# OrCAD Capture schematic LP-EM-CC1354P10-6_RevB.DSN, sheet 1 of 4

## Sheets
1 1_RF: size A3; title: LP-EM-CC1354P10-6
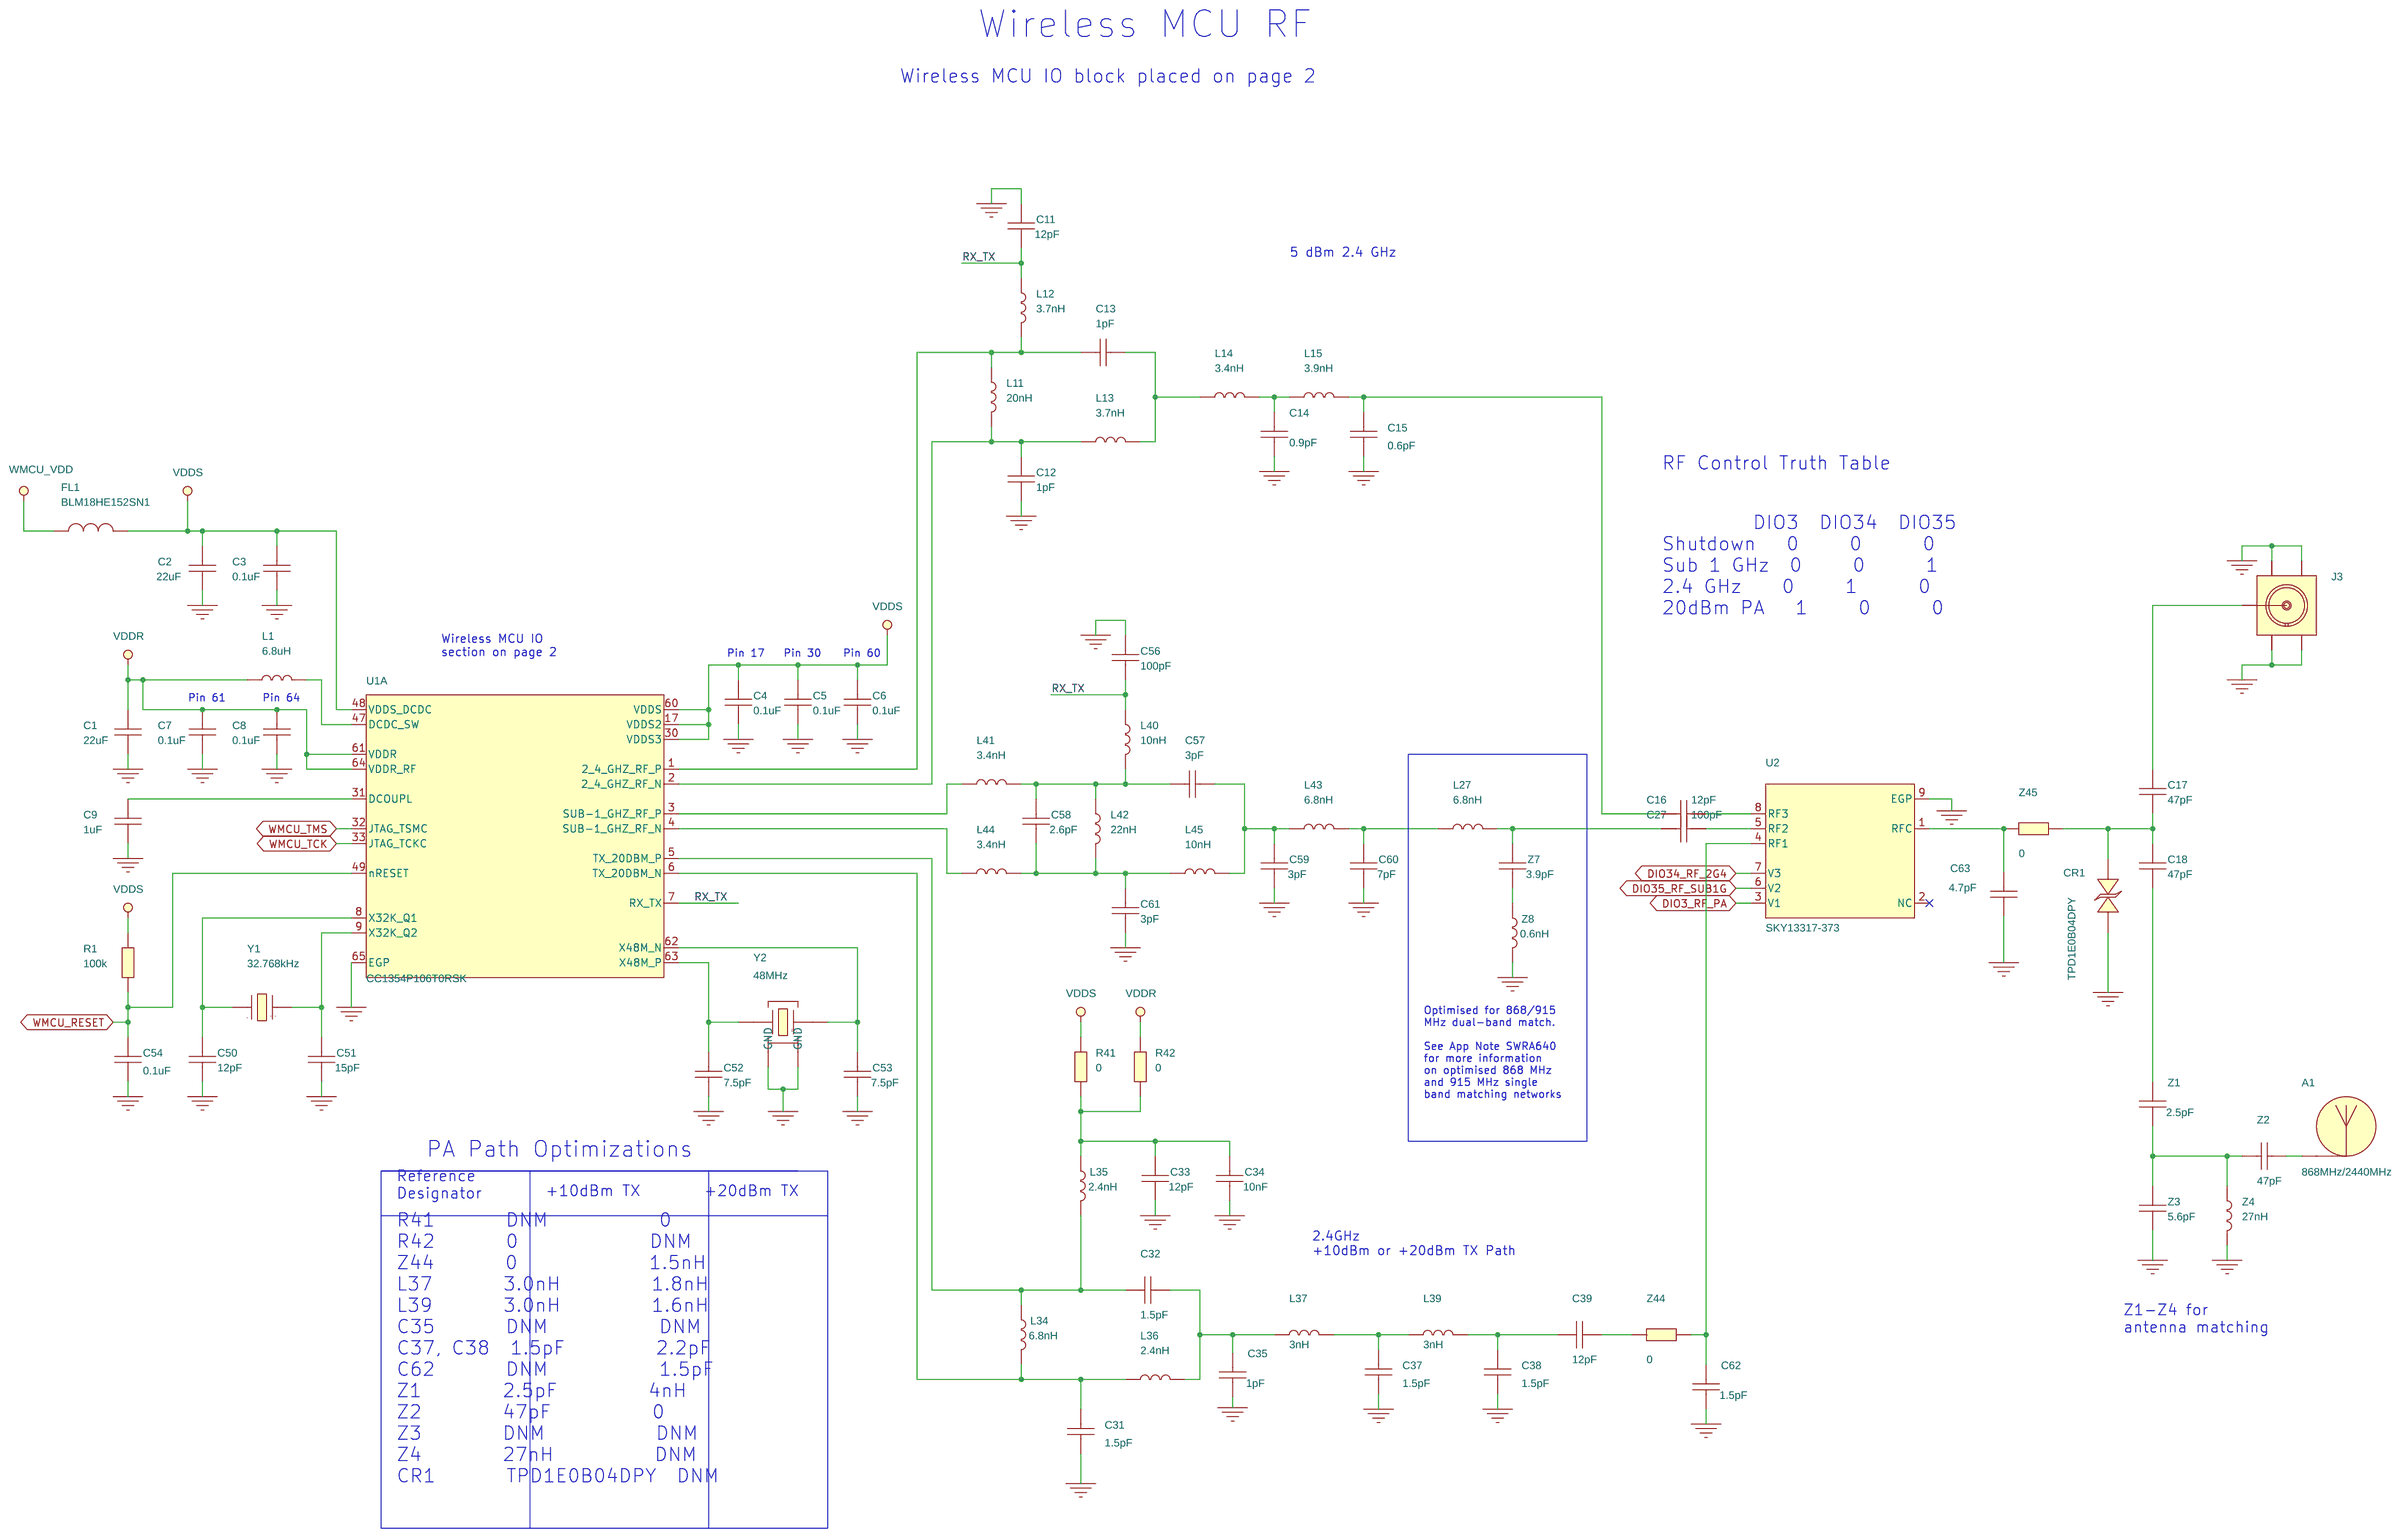
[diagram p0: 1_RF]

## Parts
A1  868MHz/2440MHz  [ANTENNA_DN024N]
C1  22uF  [CAPC1608X100A2N]
C2  22uF  [CAPC1608X100A2N]
C3  0.1uF  [CAPC0603X35B2N]
C4  0.1uF  [CAPC0603X35B2N]
C5  0.1uF  [CAPC0603X35B2N]
C6  0.1uF  [CAPC0603X35B2N]
C7  0.1uF  [CAPC0603X35B2N]
C8  0.1uF  [CAPC0603X35B2N]
C9  1uF  [CAPC0603X40B2N]
C11  12pF  [CAPC0603X35B2N]
C12  1pF  [CAPC0603X35B2N]
C13  1pF  [CAPC0603X35B2N]
C14  0.9pF  [CAPC0603X35B2N]
C15  0.6pF  [CAPC0603X35B2N]
C16  12pF  [CAPC0603X35B2N]
C17  47pF  [CAPC1005X60B2N]
C18  47pF  [CAPC1005X60B2N]
C27  100pF  [CAPC0603X35B2N]
C31  1.5pF  [CAPC0603X35B2N]
C32  1.5pF  [CAPC0603X35B2N]
C33  12pF  [CAPC0603X35B2N]
C34  10nF  [CAPC0603X35B2N]
C35  1pF  [CAPC0603X35B2N]
C37  1.5pF  [CAPC0603X35B2N]
C38  1.5pF  [CAPC0603X35B2N]
C39  12pF  [CAPC0603X35B2N]
C50  12pF  [CAPC0603X35B2N]
C51  15pF  [CAPC0603X35B2N]
C52  7.5pF  [CAPC0603X35B2N]
C53  7.5pF  [CAPC0603X35B2N]
C54  0.1uF  [CAPC0603X35B2N]
C56  100pF  [CAPC0603X35B2N]
C57  3pF  [CAPC0603X35B2N]
C58  2.6pF  [CAPC0603X35B2N]
C59  3pF  [CAPC0603X35B2N]
C60  7pF  [CAPC0603X35B2N]
C61  3pF  [CAPC0603X35B2N]
C62  1.5pF  [CAPC0603X35B2N]
C63  4.7pF  [CAPC0603X35B2N]
CR1  TPD1E0B04DPY  [SON65P100X60X45-2A2N]
FL1  BLM18HE152SN1  [FIL_BLM18HE152SN1DN]
J3  SMA-10V21-TGG  [HUSTSAN_SMA10V21TGGAN]
L1  6.8uH  [INDC2012X150A2N]
L11  20nH  [INDC0603X33A2N]
L12  3.7nH  [INDC0603X33A2N]
L13  3.7nH  [INDC0603X33A2N]
L14  3.4nH  [INDC0603X33A2N]
L15  3.9nH  [IND_LQP03HQ_A2N]
L27  6.8nH  [INDC0603X33A2N]
L34  6.8nH  [INDC0603X33A2N]
L35  2.4nH  [INDC0603X33A2N]
L36  2.4nH  [INDC0603X33A2N]
L37  3nH  [IND_LQP03HQ_A2N]
L39  3nH  [IND_LQP03HQ_A2N]
L40  10nH  [INDC0603X33A2N]
L41  3.4nH  [INDC0603X33A2N]
L42  22nH  [INDC0603X33A2N]
L43  6.8nH  [INDC0603X33A2N]
L44  3.4nH  [INDC0603X33A2N]
L45  10nH  [INDC0603X33A2N]
R1  100k  [RESC1005X40B2N]
R41  0  [RESC1005X40B2N]
R42  0  [RESC1005X40B2N]
U1  CC1354P106T0RSK  [QFNFC40P800X800X100-65A2N]  (sections A,B)
U2  SKY13317-373  [SON40P150X150X50-9A2N]
Y1  32.768kHz  [XTAL_TZ3581F_A2N]
Y2  48MHz  [OSCCC200X160X50-4A2N]
Z1  2.5pF  [CAPC0603X35B2N]
Z2  47pF  [CAPC0603X35B2N]
Z3  5.6pF  [CAPC0603X35B2N]
Z4  27nH  [INDC0603X33A2N]
Z7  3.9pF  [CAPC0603X35B2N]
Z8  0.6nH  [INDC0603X33A2N]
Z44  0  [RESC0603X35B2N]
Z45  0  [RESC0603X35B2N]

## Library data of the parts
A1 = ANTENNA_PCB: ANTENNA, NON COMPONENT, DUAL BAND OPTION - 868MHz/2440MHz, NOT APPLY; Additional Datasheet URL: N/A; AutoDoc File: https://notefied-dynamic-precision.com/DB/Apps/Desktop/Item/Object.aspx?id=96668; BU Name: DYNAMIC PRECISION GDANSK; Budget Currency: N/A; Budget Price: N/A; Client Status: UNDER_REVIEW; Country of Origin: Missing Info; Datasheet URL: https://www.ti.com/lit/an/swra227e/swra227e.pdf; Datasheet URL 1: http://www.ti.com/lit/an/swra227e/swra227e.pdf; Datasheet URL 2: N/A; Mass: N/A; Max Oper Temp: N/A; Maximum Operating Temperature: N/A; Min Oper Temp: N/A; Minimum Operating Temperature: N/A; Mounting Type: NOT APPLY; NOTEfied URL: https://notefied-dynamic-precision.com/NOTEfiedWebInterface/part/show?partNumber=13-01029; Notes: Custom component designed upon client's request.; Packing Size: N/A; Packing Type: Missing Info; Part Number: 13-01029; Part Type: Mechanic|ANTENNA|NON COMPONENT; ROHS: Not Applicable; Revision: R039; RoHS Status: MISSING_INFO; Status: Released; Texas Part Status: Under Review; Type: Mechanic; Vendor: TEXAS INSTRUMENTS; Vendor Part Number: DN024; Vendor Part Status: Active; Weight: N/A
C1 C2 = CAPACITOR: CAPACITOR, CERAMIC X6S, 22uF, 6.3V, -20%/+20%, -55DEGC/+105DEGC, 0603, SMD; ALT_SYMBOLS: CAPC1608X100A2L,CAPC1608X100A2M; Additional Datasheet URL: https://www.murata.com/en-us/products/productdetail?partno=GRM188C80J226ME15%23; AutoDoc File: https://notefied-dynamic-precision.com/DB/Apps/Desktop/Item/Object.aspx?id=104385; BU Name: DYNAMIC PRECISION GDANSK; Budget Currency: EUR; Budget Price: 0.062; Budgetary Price: 0.07648 USD; Client Status: UNDER_REVIEW; Country of Origin: China,Japan,Philippines; Datasheet URL: https://search.murata.co.jp/Ceramy/image/img/A01X/G101/ENG/GRM188C80J226ME15-02A.pdf; Datasheet URL 1: http://psearch.murata.com/capacitor/product/GRM188R60J226MEA0%23.pdf; Datasheet URL 2: http://search.murata.co.jp/Ceramy/image/img/w_hinm/L0005E.pdf; Definied Quality: INDUSTRIAL; Dielectric Type: X6S; Esd Level: N/A; Lead Time: 15; MPN: GRM188R60J106ME47D; MPN Status: NRND; MSL: 1; MTBF: N/A; MTBF Standard: N/A; Manufacturer: MURATA; Mass: 0.0091g; Max Oper Temp: +85DEGC; Max Tol: +20%; Maximum Operating Temperature: +105DEGC; Maximum Tolerance: +20%; Min Oper Temp: -55DEGC; Min Tol: -20%; Minimum Operating Temperature: -55DEGC; Minimum Tolerance: -20%; Mounting Type: SMD; NOTE Status: PREFERRED; NOTEfied URL: https://notefied-dynamic-precision.com/NOTEfiedWebInterface/part/show?partNumber=02-09737; Old Footprint: CAPC1608X90N; PCB Package: 0603; Packing Size: 4000; Packing Type: Tape & Reel; Part Number: 02-09737; Part Type: Capacitor|CERAMIC|0603|STANDARD; REACH/SVHC Compliance: Compliant; REACH/SVHC Details: SVHC List Version Jan 23, 2024 (240); REACH/SVHC Source: REACH Declaration; REACH/SVHC Status: Unaffected; REACH/SVHC_COMPLIANCE: COMPLIANT; REACH/SVHC_DETAILS: SVHC LIST VERSION Dec 17, 2015; REACH/SVHC_SOURCE: REACH DECLARATION; REACH/SVHC_STATUS: UNAFFECTED; ROHS: Compliant; Rated Current: N/A; Rated Voltage: 6.3V; Revision: R019; RoHS Status: ROHS_COMPLIANT; Rtd Voltage: 6.3V; Status: Released; Texas Part Status: Under Review; Type: Capacitor; Vendor: MURATA; Vendor Part Number: GRM188C80J226ME15D; Vendor Part Status: Active; WEIGHT: 0.0091g
C3-C8 C54 = CAPACITOR: CAPACITOR, CERAMIC X7S, 0.1uF, 10V, -10%/+10%, -55DEGC/+125DEGC, 0201, SMD; ALT_SYMBOLS: CAPC0603X35B2L,CAPC0603X35B2M; Additional Datasheet URL: https://www.murata.com/en-us/products/productdetail?partno=GRM033C71A104KE14%23; AutoDoc File: https://notefied-dynamic-precision.com/DB/Apps/Desktop/Item/Object.aspx?id=115293; BU Name: TEXAS INSTRUMENTS NORWAY; Budgetary Price: 0.01328 USD; Client Status: UNDER_REVIEW; Country of Origin: China,Japan,Philippines,Singapore; Datasheet URL: https://search.murata.co.jp/Ceramy/image/img/A01X/G101/ENG/GRM033C71A104KE14-01A.pdf; Datasheet URL 1: http://psearch.en.murata.com/capacitor/product/GRM155R71E104KE14%23.pdf; Datasheet URL 2: http://search.murata.co.jp/Ceramy/image/img/w_hinm/L0005E.pdf; Dielectric Type: X7S; Lead Time: 23; LifeCycle Status: ACTIVE; MPN: GRM155R70J104KA01D; MPN Status: ACTIVE; Manufacturer: MURATA; Mass: 0.00033g; Max Oper Temp: +125DEGC; Max Tol: +10%; Maximum Operating Temperature: +125DEGC; Maximum Tolerance: +10%; Min Oper Temp: -55DEGC; Min Tol: -10%; Minimum Operating Temperature: -55DEGC; Minimum Tolerance: -10%; Mounting Type: SMD; NOTE Status: PREFERRED; NOTEfied URL: https://notefied-dynamic-precision.com/NOTEfiedWebInterface/part/show?partNumber=02-10308; Old Footprint: CAPC1005X60N,0402; PCB Package: 0201; Packing Size: 15000; Packing Type: Tape & Reel; Part Number: 02-10308; Part Type: Capacitor|CERAMIC|0201|STANDARD; REACH/SVHC Compliance: Compliant; REACH/SVHC Details: SVHC List Version Jan 23, 2024 (240); REACH/SVHC Source: REACH Declaration; REACH/SVHC Status: Unaffected; REACH/SVHC_COMPLIANCE: COMPLIANT; REACH/SVHC_DETAILS: SVHC LIST VERSION Jun 20, 2016; REACH/SVHC_SOURCE: REACH DECLARATION; REACH/SVHC_STATUS: UNAFFECTED; ROHS: Compliant; Rated Voltage: 10V; Revision: R018; RoHS Status: ROHS_COMPLIANT; Rtd Voltage: 25V; Status: Released; Texas Part Status: Under Review; Type: Capacitor; Vendor: MURATA; Vendor Part Number: GRM033C71A104KE14D; Vendor Part Status: Active; WEIGHT: 0.0016g
C9 = CAPACITOR: CAPACITOR, CERAMIC X6S, 1uF, 6.3V, -20%/+20%, -55DEGC/+105DEGC, 0201, SMD; ALT_SYMBOLS: CAPC0603X40B2L,CAPC0603X40B2M; Additional Datasheet URL: https://www.murata.com/en-us/products/productdetail?partno=GRM033C80J105ME05%23; AutoDoc File: https://notefied-dynamic-precision.com/DB/Apps/Desktop/Item/Object.aspx?id=115295; BU Name: TEXAS INSTRUMENTS NORWAY; Budgetary Price: 0.0415 USD; Client Status: UNDER_REVIEW; Country of Origin: China,Japan,Philippines; Datasheet URL: https://search.murata.co.jp/Ceramy/image/img/A01X/G101/ENG/GRM033C80J105ME05-01A.pdf; Datasheet URL 1: http://psearch.en.murata.com/capacitor/product/GRM155R61C105KA12%23.pdf; Datasheet URL 2: http://search.murata.co.jp/Ceramy/image/img/w_hinm/L0005E.pdf; Definied Quality: INDUSTRIAL; Dielectric Type: X6S; Esd Level: N/A; Lead Time: 11; MPN: GRM155R61A105KE15D; MPN Status: ACTIVE; MSL: 1; MTBF: N/A; MTBF Standard: N/A; Manufacturer: MURATA; Mass: 0.00033g; Max Oper Temp: +85DEGC; Max Tol: +10%; Maximum Operating Temperature: +105DEGC; Maximum Tolerance: +20%; Min Oper Temp: -55DEGC; Min Tol: -10%; Minimum Operating Temperature: -55DEGC; Minimum Tolerance: -20%; Mounting Type: SMD; NOTE Status: PREFERRED; NOTEfied URL: https://notefied-dynamic-precision.com/NOTEfiedWebInterface/part/show?partNumber=02-09405; Old Footprint: CAPC1005X60N,0402; PCB Package: 0201; Packing Size: 15000; Packing Type: Tape & Reel; Part Number: 02-09405; Part Type: Capacitor|CERAMIC|0201|STANDARD; REACH/SVHC Compliance: Compliant; REACH/SVHC Details: SVHC List Version Jan 23, 2024 (240); REACH/SVHC Source: REACH Declaration; REACH/SVHC Status: Unaffected; REACH/SVHC_COMPLIANCE: COMPLIANT; REACH/SVHC_DETAILS: SVHC LIST VERSION Jun 20, 2016; REACH/SVHC_SOURCE: REACH DECLARATION; REACH/SVHC_STATUS: UNAFFECTED; ROHS: Compliant; Rated Voltage: 6.3V; Revision: R024; RoHS Status: ROHS_COMPLIANT; Rtd Voltage: 16V; Status: Released; Texas Part Status: Under Review; Type: Capacitor; Vendor: MURATA; Vendor Part Number: GRM033C80J105ME05D; Vendor Part Status: Active; WEIGHT: 0.0016g
C11 C16 = CAPACITOR: CAPACITOR, CERAMIC C0G/NP0, 12pF, 50V, -2%/+2%, -55DEGC/+125DEGC, 0201, SMD; ALT_SYMBOLS: CAPC0603X35B2L,CAPC0603X35B2M; Additional Datasheet URL: https://search.murata.co.jp/Ceramy/image/img/A01X/G101/ENG/GRM0335C1H120GA01-01A.pdf; Budgetary Price: 0.00506 USD; Datasheet URL: https://www.murata.com/-/media/webrenewal/support/library/catalog/products/capacitor/ceramiccapacitor/c02e.ashx?la=en-gb&cvid=20210120024548000000; Dielectric Type: C0G/NP0; Lead Time: 23; Mass: 0.00033g; Maximum Operating Temperature: +125DEGC; Maximum Tolerance: +2%; Minimum Operating Temperature: -55DEGC; Minimum Tolerance: -2%; Mounting Type: SMD; NOTEfied URL: https://notefied-dynamic-precision.com/NOTEfiedWebInterface/part/show?partNumber=02-10307; PCB Package: 0201; Packing Size: 15000; Packing Type: Tape & Reel; Part Number: 02-10307; Part Type: Capacitor|CERAMIC|0201|STANDARD; REACH/SVHC Compliance: Compliant; REACH/SVHC Details: SVHC List Version Jan 19, 2021; REACH/SVHC Source: REACH Declaration; REACH/SVHC Status: Unaffected; ROHS: Compliant; Rated Voltage: 50V; Revision: R001; Status: Released; Texas Part Status: Under Review; Type: Capacitor; Vendor: MURATA; Vendor Part Number: GRM0335C1H120GA01D; Vendor Part Status: Active
C12 C13 = CAPACITOR: CAPACITOR, CERAMIC C0G/NP0, 1pF, 50V, -0.1pF/+0.1pF, -55DEGC/+125DEGC, 0201, SMD; ALT_SYMBOLS: CAPC0603X35B2L,CAPC0603X35B2M; Additional Datasheet URL: https://search.murata.co.jp/Ceramy/image/img/A01X/G101/ENG/GRM0335C1H1R0BA01-01A.pdf; AutoDoc File: https://notefied-dynamic-precision.com/DB/Apps/Desktop/Item/Object.aspx?id=97010; BU Name: DYNAMIC PRECISION GDANSK; Budget Currency: EUR; Budget Price: 0.00597; Budgetary Price: 0.01 EUR; Client Status: UNDER_REVIEW; Country of Origin: Missing Info; Datasheet URL: https://www.murata.com/-/media/webrenewal/support/library/catalog/products/capacitor/mlcc/c02e.ashx?la=en-gb; Datasheet URL 1: http://psearch.murata.com/capacitor/product/GRM0335C1H1R1BA01%23.pdf; Datasheet URL 2: http://psearch.en.murata.com/capacitor/product/GRM0335C1H1R1BA01%23.html; Dielectric Type: C0G/NP0; Lead Time: 24; MPN: GRM1555C1H1R0CA01D; MPN Status: ACTIVE; Manufacturer: MURATA; Mass: 0.00033g; Max Oper Temp: +125DEGC; Max Tol: +0.1pF; Maximum Operating Temperature: +125DEGC; Maximum Tolerance: +0.1pF; Min Oper Temp: -55DEGC; Min Tol: -0.1pF; Minimum Operating Temperature: -55DEGC; Minimum Tolerance: -0.1pF; Mounting Type: SMD; NOTE Status: PREFERRED; NOTEfied URL: https://notefied-dynamic-precision.com/NOTEfiedWebInterface/part/show?partNumber=02-06124; Old Footprint: CAPC1005X60N; PCB Package: 0201; Packing Size: 50000; Packing Type: Tape & Reel; Part Number: 02-06124; Part Type: Capacitor|CERAMIC|0201|STANDARD; REACH/SVHC Compliance: Compliant; REACH/SVHC Details: SVHC List Version Jul 7, 2017; REACH/SVHC Source: REACH Declaration; REACH/SVHC Status: Unaffected; REACH/SVHC_COMPLIANCE: COMPLIANT; REACH/SVHC_DETAILS: SVHC List Version Jan 12, 2017; REACH/SVHC_SOURCE: REACH DECLARATION; REACH/SVHC_STATUS: UNAFFECTED; ROHS: Compliant; Rated Voltage: 50V; Revision: R025; RoHS Status: ROHS_COMPLIANT; Rtd Voltage: 50V; Status: Released; Texas Part Status: Under Review; Type: Capacitor; Vendor: MURATA; Vendor Part Number: GRM0335C1H1R0BA01J; Vendor Part Status: Active; WEIGHT: 0.00033g
C14 = CAPACITOR: CAPACITOR, CERAMIC C0G/NP0, 0.9pF, 50V, -0.1pF/+0.1pF, -55DEGC/+125DEGC, 0201, SMD; ALT_SYMBOLS: CAPC0603X35B2L,CAPC0603X35B2M; Additional Datasheet URL: https://www.murata.com/en-us/products/productdetail?partno=GRM0335C1HR90BA01%23; Budgetary Price: 0.00272 USD; Country of Origin: China,Japan; Datasheet URL: https://search.murata.co.jp/Ceramy/image/img/A01X/G101/ENG/GRM0335C1HR90BA01-01A.pdf; Dielectric Type: C0G/NP0; Lead Time: 11; Mass: 0.00033g; Maximum Operating Temperature: +125DEGC; Maximum Tolerance: +0.1pF; Minimum Operating Temperature: -55DEGC; Minimum Tolerance: -0.1pF; Mounting Type: SMD; NOTEfied URL: https://notefied-dynamic-precision.com/NOTEfiedWebInterface/part/show?partNumber=02-06123; PCB Package: 0201; Packing Size: 50000; Packing Type: Tape & Reel; Part Number: 02-06123; Part Type: Capacitor|CERAMIC|0201|STANDARD; REACH/SVHC Compliance: Compliant; REACH/SVHC Details: SVHC List Version Jan 23, 2024 (240); REACH/SVHC Source: REACH Declaration; REACH/SVHC Status: Unaffected; ROHS: Compliant; Rated Voltage: 50V; Revision: R041; Status: Released; Texas Part Status: Under Review; Type: Capacitor; Vendor: MURATA; Vendor Part Number: GRM0335C1HR90BA01J; Vendor Part Status: Active
C15 = CAPACITOR: CAPACITOR, CERAMIC C0G/NP0, 0.6pF, 50V, -0.1pF/+0.1pF, -55DEGC/+125DEGC, 0201, SMD; ALT_SYMBOLS: CAPC0603X35B2L,CAPC0603X35B2M; Additional Datasheet URL: https://www.murata.com/en-us/products/productdetail?partno=GRM0335C1HR60BA01%23; Budgetary Price: 0.00272 USD; Country of Origin: China,Japan; Datasheet URL: https://search.murata.co.jp/Ceramy/image/img/A01X/G101/ENG/GRM0335C1HR60BA01-01A.pdf; Dielectric Type: C0G/NP0; Lead Time: 11; Mass: 0.00033g; Maximum Operating Temperature: +125DEGC; Maximum Tolerance: +0.1pF; Minimum Operating Temperature: -55DEGC; Minimum Tolerance: -0.1pF; Mounting Type: SMD; NOTEfied URL: https://notefied-dynamic-precision.com/NOTEfiedWebInterface/part/show?partNumber=02-06120; PCB Package: 0201; Packing Size: 50000; Packing Type: Tape & Reel; Part Number: 02-06120; Part Type: Capacitor|CERAMIC|0201|STANDARD; REACH/SVHC Compliance: Compliant; REACH/SVHC Details: SVHC List Version Jan 23, 2024 (240); REACH/SVHC Source: REACH Declaration; REACH/SVHC Status: Unaffected; ROHS: Compliant; Rated Voltage: 50V; Revision: R041; Status: Released; Texas Part Status: Under Review; Type: Capacitor; Vendor: MURATA; Vendor Part Number: GRM0335C1HR60BA01J; Vendor Part Status: Active
C17 = CAPACITOR: CAPACITOR, CERAMIC C0G/NP0, 47pF, 50V, -5%/+5%, -55DEGC/+125DEGC, 0402, SMD; Additional Datasheet URL: https://search.murata.co.jp/Ceramy/image/img/A01X/G101/ENG/GCM1555C1H470JA16-01.pdf; AutoDoc File: https://notefied-dynamic-precision.com/DB/Apps/Desktop/Item/Object.aspx?id=113344; BU Name: TEXAS INSTRUMENTS NORWAY; Budgetary Price: 0.01416 USD; Datasheet URL: https://www.murata.com/-/media/webrenewal/support/library/catalog/products/capacitor/ceramiccapacitor/c03e.ashx?la=en-gb&cvid=20200707014404000000; Datasheet URL 1: N/A; Datasheet URL 2: N/A; Dielectric Type: C0G/NP0; Lead Time: 27; Mass: 0.0016g; Max Oper Temp: +125DEGC; Maximum Operating Temperature: +125DEGC; Maximum Tolerance: +5%; Min Oper Temp: -55DEGC; Minimum Operating Temperature: -55DEGC; Minimum Tolerance: -5%; Mounting Type: SMD; NOTEfied URL: https://notefied-dynamic-precision.com/NOTEfiedWebInterface/part/show?partNumber=02-10309; PCB Package: 0402; Packing Size: 50000; Packing Type: Tape & Reel; Part Number: 02-10309; Part Type: Capacitor|CERAMIC|0402|STANDARD; REACH/SVHC Compliance: Compliant; REACH/SVHC Details: SVHC List Version Jan 19, 2021; REACH/SVHC Source: REACH Declaration; REACH/SVHC Status: Unaffected; ROHS: Compliant; Rated Voltage: 50V; Revision: R001; RoHS Status: ROHS_COMPLIANT; Status: Released; Texas Part Status: Under Review; Type: Capacitor; Vendor: MURATA; Vendor Part Number: GCM1555C1H470JA16J; Vendor Part Status: Active; Weight: N/A
C18 = CAPACITOR: CAPACITOR, CERAMIC C0G/NP0, 47pF, 50V, -5%/+5%, -55DEGC/+125DEGC, 0402, SMD; Additional Datasheet URL: https://search.murata.co.jp/Ceramy/image/img/A01X/G101/ENG/GCM1555C1H470JA16-01.pdf; Budgetary Price: 0.01416 USD; Datasheet URL: https://www.murata.com/-/media/webrenewal/support/library/catalog/products/capacitor/ceramiccapacitor/c03e.ashx?la=en-gb&cvid=20200707014404000000; Dielectric Type: C0G/NP0; Lead Time: 27; Mass: 0.0016g; Maximum Operating Temperature: +125DEGC; Maximum Tolerance: +5%; Minimum Operating Temperature: -55DEGC; Minimum Tolerance: -5%; Mounting Type: SMD; NOTEfied URL: https://notefied-dynamic-precision.com/NOTEfiedWebInterface/part/show?partNumber=02-10309; PCB Package: 0402; Packing Size: 50000; Packing Type: Tape & Reel; Part Number: 02-10309; Part Type: Capacitor|CERAMIC|0402|STANDARD; REACH/SVHC Compliance: Compliant; REACH/SVHC Details: SVHC List Version Jan 19, 2021; REACH/SVHC Source: REACH Declaration; REACH/SVHC Status: Unaffected; ROHS: Compliant; Rated Voltage: 50V; Revision: R001; Status: Released; Texas Part Status: Under Review; Type: Capacitor; Vendor: MURATA; Vendor Part Number: GCM1555C1H470JA16J; Vendor Part Status: Active
C27 = CAPACITOR: CAPACITOR, CERAMIC C0G/NP0, 100pF, 50V, -2%/+2%, -55DEGC/+125DEGC, 0201, SMD; ALT_SYMBOLS: CAPC0603X35B2L,CAPC0603X35B2M; Additional Datasheet URL: https://search.murata.co.jp/Ceramy/image/img/A01X/G101/ENG/GRM0335C1H101GA01-01A.pdf; AutoDoc File: https://notefied-dynamic-precision.com/DB/Apps/Desktop/Item/Object.aspx?id=116466; BU Name: DYNAMIC PRECISION GDANSK; Budgetary Price: 0.0032 USD; Client Status: UNDER_REVIEW; Country of Origin: China,Philippines; Datasheet URL: https://www.murata.com/-/media/webrenewal/support/library/catalog/products/capacitor/mlcc/c02e.ashx?la=en-gb; Datasheet URL 1: http://www.murata.com/~/media/webrenewal/support/library/catalog/products/capacitor/mlcc/c02e.ashx?la=en-gb; Datasheet URL 2: http://psearch.en.murata.com/capacitor/product/GRM0335C1H101GA01%23.pdf; Dielectric Type: C0G/NP0; Lead Time: 11; Mass: 0.00033g; Max Oper Temp: +125DEGC; Max Tol: +2%; Maximum Operating Temperature: +125DEGC; Maximum Tolerance: +2%; Min Oper Temp: -55DEGC; Min Tol: -2%; Minimum Operating Temperature: -55DEGC; Minimum Tolerance: -2%; Mounting Type: SMD; NOTEfied URL: https://notefied-dynamic-precision.com/NOTEfiedWebInterface/part/show?partNumber=02-07975; PCB Package: 0201; Packing Size: 15000; Packing Type: Tape & Reel; Part Number: 02-07975; Part Type: Capacitor|CERAMIC|0201|STANDARD; ROHS: Compliant; Rated Voltage: 50V; Revision: R021; RoHS Status: ROHS_COMPLIANT; Rtd Voltage: 50V; Status: Released; Type: Capacitor; Vendor: MURATA; Vendor Part Number: GRM0335C1H101GA01D; Vendor Part Status: Active; Weight: 0.00033g
C31 C32 C37 C38 = CAPACITOR: CAPACITOR, CERAMIC C0G/NP0, 1.5pF, 50V, -0.1pF/+0.1pF, -55DEGC/+125DEGC, 0201, SMD; ALT_SYMBOLS: CAPC0603X35B2L,CAPC0603X35B2M; Additional Datasheet URL: https://www.murata.com/en-us/products/productdetail?partno=GRM0335C1H1R5BA01%23; Budgetary Price: 0.00272 USD; Country of Origin: China,Japan,Philippines; Datasheet URL: https://search.murata.co.jp/Ceramy/image/img/A01X/G101/ENG/GRM0335C1H1R5BA01-01A.pdf; Dielectric Type: C0G/NP0; Lead Time: 11; Mass: 0.00033g; Maximum Operating Temperature: +125DEGC; Maximum Tolerance: +0.1pF; Minimum Operating Temperature: -55DEGC; Minimum Tolerance: -0.1pF; Mounting Type: SMD; NOTEfied URL: https://notefied-dynamic-precision.com/NOTEfiedWebInterface/part/show?partNumber=02-06129; PCB Package: 0201; Packing Size: 50000; Packing Type: Tape & Reel; Part Number: 02-06129; Part Type: Capacitor|CERAMIC|0201|STANDARD; REACH/SVHC Compliance: Compliant; REACH/SVHC Details: SVHC List Version Jan 23, 2024 (240); REACH/SVHC Source: REACH Declaration; REACH/SVHC Status: Unaffected; ROHS: Compliant; Rated Voltage: 50V; Revision: R041; Status: Released; Texas Part Status: Under Review; Type: Capacitor; Vendor: MURATA; Vendor Part Number: GRM0335C1H1R5BA01J; Vendor Part Status: Active
C33 C39 = CAPACITOR: CAPACITOR, CERAMIC C0G/NP0, 12pF, 50V, -1%/+1%, -55DEGC/+125DEGC, 0201, SMD; ALT_SYMBOLS: CAPC0603X35B2L,CAPC0603X35B2M; Additional Datasheet URL: https://www.murata.com/en-us/products/productdetail?partno=GRT0335C1H120FA02%23; Budgetary Price: 0.00504 USD; Country of Origin: Missing Info; Datasheet URL: https://search.murata.co.jp/Ceramy/image/img/A01X/G101/ENG/GRT0335C1H120FA02-01A.pdf; Dielectric Type: C0G/NP0; Lead Time: 148; Mass: 0.00033g; Maximum Operating Temperature: +125DEGC; Maximum Tolerance: +1%; Minimum Operating Temperature: -55DEGC; Minimum Tolerance: -1%; Mounting Type: SMD; NOTEfied URL: https://notefied-dynamic-precision.com/NOTEfiedWebInterface/part/show?partNumber=02-10513; PCB Package: 0201; Packing Size: 15000; Packing Type: Tape & Reel; Part Number: 02-10513; Part Type: Capacitor|CERAMIC|0201|PRECISION; REACH/SVHC Compliance: Compliant; REACH/SVHC Details: SVHC List Version Jan 23, 2024 (240); REACH/SVHC Source: REACH Declaration; REACH/SVHC Status: Unaffected; ROHS: Compliant; Rated Voltage: 50V; Revision: R015; Status: Released; Texas Part Status: Under Review; Type: Capacitor; Vendor: MURATA; Vendor Part Number: GRT0335C1H120FA02D; Vendor Part Status: Active
C34 = CAPACITOR: CAPACITOR, CERAMIC X7R, 10nF, 10V, -10%/+10%, -55DEGC/+125DEGC, 0201, SMD; ALT_SYMBOLS: CAPC0603X35B2L,CAPC0603X35B2M; Additional Datasheet URL: https://www.murata.com/en-us/products/productdetail?partno=GRM033R71A103KA01%23; AutoDoc File: https://notefied-dynamic-precision.com/DB/Apps/Desktop/Item/Object.aspx?id=49750; BU Name: DYNAMIC PRECISION GDANSK; Budget Currency: EUR; Budget Price: 0.007; Budgetary Price: 0.0042 USD; Client Status: UNDER_REVIEW; Country of Origin: China,Japan,Philippines; Datasheet URL: https://search.murata.co.jp/Ceramy/image/img/A01X/G101/ENG/GRM033R71A103KA01-01A.pdf; Datasheet URL 1: http://psearch.murata.com/capacitor/product/GRM033R71A103KA01%23.pdf; Datasheet URL 2: http://search.murata.co.jp/Ceramy/image/img/w_hinm/L0005E.pdf; Dielectric Type: X7R; Lead Time: 11; Mass: 0.00033g; Max Oper Temp: +125DEGC; Max Tol: +10%; Maximum Operating Temperature: +125DEGC; Maximum Tolerance: +10%; Min Oper Temp: -55DEGC; Min Tol: -10%; Minimum Operating Temperature: -55DEGC; Minimum Tolerance: -10%; Mounting Type: SMD; NOTEfied URL: https://notefied-dynamic-precision.com/NOTEfiedWebInterface/part/show?partNumber=02-00599; PCB Package: 0201; Packing Size: 15000; Packing Type: Tape & Reel; Part Number: 02-00599; Part Type: Capacitor|CERAMIC|0201|STANDARD; REACH/SVHC Compliance: Compliant; REACH/SVHC Details: SVHC List Version Jan 23, 2024 (240); REACH/SVHC Source: REACH Declaration & Material Declaration; REACH/SVHC Status: Unaffected; REACH/SVHC_COMPLIANCE: COMPLIANT; REACH/SVHC_DETAILS: SVHC List Version Jan 12, 2017; REACH/SVHC_SOURCE: REACH DECLARATION; REACH/SVHC_STATUS: UNAFFECTED; ROHS: Compliant; Rated Voltage: 10V; Revision: R049; RoHS Status: ROHS_COMPLIANT; Rtd Voltage: 10V; Status: Released; Type: Capacitor; Vendor: MURATA; Vendor Part Number: GRM033R71A103KA01D; Vendor Part Status: Active; Weight: 0.00033g
C35 = CAPACITOR: CAPACITOR, CERAMIC C0G/NP0, 1pF, 50V, -0.1pF/+0.1pF, -55DEGC/+125DEGC, 0201, SMD; ALT_SYMBOLS: CAPC0603X35B2L,CAPC0603X35B2M; Additional Datasheet URL: https://www.murata.com/en-eu/products/productdetail?partno=GRM0335C1H1R0BA01%23; Budgetary Price: 0.01 EUR; Country of Origin: China,Japan,Philippines; Datasheet URL: https://search.murata.co.jp/Ceramy/image/img/A01X/G101/ENG/GRM0335C1H1R0BA01-01A.pdf; Dielectric Type: C0G/NP0; Lead Time: 24; Mass: 0.00033g; Maximum Operating Temperature: +125DEGC; Maximum Tolerance: +0.1pF; Minimum Operating Temperature: -55DEGC; Minimum Tolerance: -0.1pF; Mounting Type: SMD; NOTEfied URL: https://notefied-dynamic-precision.com/NOTEfiedWebInterface/part/show?partNumber=02-06124; PCB Package: 0201; Packing Size: 50000; Packing Type: Tape & Reel; Part Number: 02-06124; Part Type: Capacitor|CERAMIC|0201|STANDARD; REACH/SVHC Compliance: Compliant; REACH/SVHC Details: SVHC List Version Jul 7, 2017; REACH/SVHC Source: REACH Declaration; REACH/SVHC Status: Unaffected; ROHS: Compliant; Rated Voltage: 50V; Revision: R037; Status: Released; Texas Part Status: Under Review; Type: Capacitor; Vendor: MURATA; Vendor Part Number: GRM0335C1H1R0BA01J; Vendor Part Status: Active
C50 = CAPACITOR: CAPACITOR, CERAMIC C0G/NP0, 12pF, 50V, -2%/+2%, -55DEGC/+125DEGC, 0201, SMD; ALT_SYMBOLS: CAPC0603X35B2L,CAPC0603X35B2M; Additional Datasheet URL: https://www.murata.com/en-us/products/productdetail?partno=GRM0335C1H120GA01%23; AutoDoc File: https://notefied-dynamic-precision.com/DB/Apps/Desktop/Item/Object.aspx?id=113345; BU Name: TEXAS INSTRUMENTS NORWAY; Budget Currency: EUR; Budget Price: 0.007; Budgetary Price: 0.00506 USD; Country of Origin: China,Japan,Philippines; Datasheet URL: https://search.murata.co.jp/Ceramy/image/img/A01X/G101/ENG/GRM0335C1H120GA01-01A.pdf; Datasheet URL 1: http://psearch.murata.com/capacitor/product/GRM1555C1H120JA01%23.pdf; Datasheet URL 2: http://search.murata.co.jp/Ceramy/image/img/w_hinm/L0005E.pdf; Definied Quality: INDUSTRIAL; Dielectric Type: C0G/NP0; Esd Level: N/A; Lead Time: 23; LifeCycle Status: ACTIVE; MPN: CAPACITOR_0402_12pF_C0G/NP0_M_+/-5%_50V; MPN Status: ACTIVE; MSL: N/A; MTBF: N/A; MTBF Standard: N/A; Manufacturer: MANUFACTURER SELECTION; Mass: 0.00033g; Max Oper Temp: +125DEGC; Max Tol: +5%; Maximum Operating Temperature: +125DEGC; Maximum Tolerance: +2%; Min Oper Temp: -55DEGC; Min Tol: -5%; Minimum Operating Temperature: -55DEGC; Minimum Tolerance: -2%; Mounting Type: SMD; NOTE Status: PREFERRED; NOTEfied URL: https://notefied-dynamic-precision.com/NOTEfiedWebInterface/part/show?partNumber=02-10307; Old Footprint: CAPC1005X60N; PCB Package: 0201; Packing Size: 15000; Packing Type: Tape & Reel; Part Number: 02-10307; Part Type: Capacitor|CERAMIC|0201|STANDARD; REACH/SVHC Compliance: Compliant; REACH/SVHC Details: SVHC List Version Jan 23, 2024 (240); REACH/SVHC Source: REACH Declaration; REACH/SVHC Status: Unaffected; REACH/SVHC_COMPLIANCE: COMPLIANT; REACH/SVHC_DETAILS: SVHC LIST VERSION Dec 17, 2015; REACH/SVHC_SOURCE: REACH DECLARATION; REACH/SVHC_STATUS: UNAFFECTED; ROHS: Compliant; Rated Voltage: 50V; Revision: R019; RoHS Status: ROHS_COMPLIANT; Rtd Voltage: 50V; Status: Released; Texas Part Status: Under Review; Type: Capacitor; Vendor: MURATA; Vendor Part Number: GRM0335C1H120GA01D; Vendor Part Status: Active; WEIGHT: 0.0016g
C51 = CAPACITOR: CAPACITOR, CERAMIC C0G/NP0, 15pF, 50V, -2%/+2%, -55DEGC/+125DEGC, 0201, SMD; ALT_SYMBOLS: CAPC0603X35B2L,CAPC0603X35B2M; Additional Datasheet URL: https://www.murata.com/en-us/products/productdetail?partno=GRM0335C1H150GA01%23; AutoDoc File: https://notefied-dynamic-precision.com/DB/Apps/Desktop/Item/Object.aspx?id=114571; BU Name: TEXAS INSTRUMENTS NORWAY; Budget Currency: EUR; Budget Price: 0.006; Budgetary Price: 0.0032 USD; Client Status: UNDER_REVIEW; Country of Origin: China,Japan,Philippines; Datasheet URL: https://search.murata.co.jp/Ceramy/image/img/A01X/G101/ENG/GRM0335C1H150GA01-01A.pdf; Datasheet URL 1: http://psearch.murata.com/capacitor/product/GRM1555C1H150JA01%23.pdf; Datasheet URL 2: http://psearch.en.murata.com/capacitor/product/GRM1555C1H150JA01%23.html; Definied Quality: INDUSTRIAL; Dielectric Type: C0G/NP0; Esd Level: N/A; Lead Time: 11; LifeCycle Status: ACTIVE; MPN: CAPACITOR_0402_12pF_C0G/NP0_M_+/-5%_50V; MPN Status: ACTIVE; MSL: N/A; MTBF: N/A; MTBF Standard: N/A; Manufacturer: MANUFACTURER SELECTION; Mass: 0.00033g; Max Oper Temp: +125DEGC; Max Tol: +5%; Maximum Operating Temperature: +125DEGC; Maximum Tolerance: +2%; Min Oper Temp: -55DEGC; Min Tol: -5%; Minimum Operating Temperature: -55DEGC; Minimum Tolerance: -2%; Mounting Type: SMD; NOTE Status: PREFERRED; NOTEfied URL: https://notefied-dynamic-precision.com/NOTEfiedWebInterface/part/show?partNumber=02-09323; Old Footprint: CAPC1005X60N; PCB Package: 0201; Packing Size: 15000; Packing Type: Tape & Reel; Part Number: 02-09323; Part Type: Capacitor|CERAMIC|0201|STANDARD; REACH/SVHC Compliance: Compliant; REACH/SVHC Details: SVHC List Version Jan 23, 2024 (240); REACH/SVHC Source: REACH Declaration; REACH/SVHC Status: Unaffected; REACH/SVHC_COMPLIANCE: COMPLIANT; REACH/SVHC_DETAILS: SVHC List Version Jan 12, 2017; REACH/SVHC_SOURCE: REACH DECLARATION; REACH/SVHC_STATUS: UNAFFECTED; ROHS: Compliant; Rated Voltage: 50V; Revision: R024; RoHS Status: ROHS_COMPLIANT; Rtd Voltage: 50V; Status: Released; Texas Part Status: Under Review; Type: Capacitor; Vendor: MURATA; Vendor Part Number: GRM0335C1H150GA01D; Vendor Part Status: Active; WEIGHT: 0.0016g
C52 C53 = CAPACITOR: CAPACITOR, CERAMIC C0G/NP0, 7.5pF, 50V, -0.1pF/+0.1pF, -55DEGC/+125DEGC, 0201, SMD; ALT_SYMBOLS: CAPC0603X35B2L,CAPC0603X35B2M; Additional Datasheet URL: https://www.murata.com/en-us/products/productdetail?partno=GRM0335C1H7R5BA01%23; Budgetary Price: 0.00221 USD; Country of Origin: China,Japan,Philippines; Datasheet URL: https://search.murata.co.jp/Ceramy/image/img/A01X/G101/ENG/GRM0335C1H7R5BA01-01A.pdf; Dielectric Type: C0G/NP0; Lead Time: 11; Mass: 0.00033g; Maximum Operating Temperature: +125DEGC; Maximum Tolerance: +0.1pF; Minimum Operating Temperature: -55DEGC; Minimum Tolerance: -0.1pF; Mounting Type: SMD; NOTEfied URL: https://notefied-dynamic-precision.com/NOTEfiedWebInterface/part/show?partNumber=02-06189; PCB Package: 0201; Packing Size: 50000; Packing Type: Tape & Reel; Part Number: 02-06189; Part Type: Capacitor|CERAMIC|0201|STANDARD; REACH/SVHC Compliance: Compliant; REACH/SVHC Details: SVHC List Version Jan 23, 2024 (240); REACH/SVHC Source: REACH Declaration; REACH/SVHC Status: Unaffected; ROHS: Compliant; Rated Voltage: 50V; Revision: R041; Status: Released; Texas Part Status: Under Review; Type: Capacitor; Vendor: MURATA; Vendor Part Number: GRM0335C1H7R5BA01J; Vendor Part Status: Active
C56 = CAPACITOR: CAPACITOR, CERAMIC C0G/NP0, 100pF, 50V, -2%/+2%, -55DEGC/+125DEGC, 0201, SMD; ALT_SYMBOLS: CAPC0603X35B2L,CAPC0603X35B2M; Additional Datasheet URL: https://www.murata.com/en-us/products/productdetail?partno=GRM0335C1H101GA01%23; AutoDoc File: https://notefied-dynamic-precision.com/DB/Apps/Desktop/Item/Object.aspx?id=116466; BU Name: DYNAMIC PRECISION GDANSK; Budgetary Price: 0.0032 USD; Client Status: UNDER_REVIEW; Country of Origin: China,Japan,Philippines; Datasheet URL: https://search.murata.co.jp/Ceramy/image/img/A01X/G101/ENG/GRM0335C1H101GA01-01A.pdf; Datasheet URL 1: http://www.murata.com/~/media/webrenewal/support/library/catalog/products/capacitor/mlcc/c02e.ashx?la=en-gb; Datasheet URL 2: http://psearch.en.murata.com/capacitor/product/GRM0335C1H101GA01%23.pdf; Dielectric Type: C0G/NP0; Lead Time: 11; Mass: 0.00033g; Max Oper Temp: +125DEGC; Max Tol: +2%; Maximum Operating Temperature: +125DEGC; Maximum Tolerance: +2%; Min Oper Temp: -55DEGC; Min Tol: -2%; Minimum Operating Temperature: -55DEGC; Minimum Tolerance: -2%; Mounting Type: SMD; NOTEfied URL: https://notefied-dynamic-precision.com/NOTEfiedWebInterface/part/show?partNumber=02-07975; PCB Package: 0201; Packing Size: 15000; Packing Type: Tape & Reel; Part Number: 02-07975; Part Type: Capacitor|CERAMIC|0201|STANDARD; ROHS: Compliant; Rated Voltage: 50V; Revision: R034; RoHS Status: ROHS_COMPLIANT; Rtd Voltage: 50V; Status: Released; Type: Capacitor; Vendor: MURATA; Vendor Part Number: GRM0335C1H101GA01D; Vendor Part Status: Active; Weight: 0.00033g
C57 C61 = CAPACITOR: CAPACITOR, CERAMIC C0G/NP0, 3pF, 50V, -0.1pF/+0.1pF, -55DEGC/+125DEGC, 0201, SMD; ALT_SYMBOLS: CAPC0603X35B2L,CAPC0603X35B2M; Additional Datasheet URL: https://www.murata.com/en-us/products/productdetail?partno=GRM0335C1H3R0BA01%23; AutoDoc File: https://notefied-dynamic-precision.com/DB/Apps/Desktop/Item/Object.aspx?id=97029; BU Name: DYNAMIC PRECISION GDANSK; Budget Currency: EUR; Budget Price: 0.006; Budgetary Price: 0.00272 USD; Client Status: UNDER_REVIEW; Country of Origin: China,Japan,Philippines; Datasheet URL: https://search.murata.co.jp/Ceramy/image/img/A01X/G101/ENG/GRM0335C1H3R0BA01-01A.pdf; Datasheet URL 1: http://psearch.murata.com/capacitor/product/GRM0335C1H3R0BA01%23.pdf; Datasheet URL 2: http://psearch.en.murata.com/capacitor/product/GRM0335C1H3R0BA01%23.html; Dielectric Type: C0G/NP0; Lead Time: 11; Mass: 0.00033g; Max Oper Temp: +125DEGC; Max Tol: +0.1pF; Maximum Operating Temperature: +125DEGC; Maximum Tolerance: +0.1pF; Min Oper Temp: -55DEGC; Min Tol: -0.1pF; Minimum Operating Temperature: -55DEGC; Minimum Tolerance: -0.1pF; Mounting Type: SMD; NOTEfied URL: https://notefied-dynamic-precision.com/NOTEfiedWebInterface/part/show?partNumber=02-06144; PCB Package: 0201; Packing Size: 50000; Packing Type: Tape & Reel; Part Number: 02-06144; Part Type: Capacitor|CERAMIC|0201|STANDARD; REACH/SVHC Compliance: Compliant; REACH/SVHC Details: SVHC List Version Jan 23, 2024 (240); REACH/SVHC Source: REACH Declaration; REACH/SVHC Status: Unaffected; REACH/SVHC_COMPLIANCE: COMPLIANT; REACH/SVHC_DETAILS: SVHC List Version Jan 12, 2017; REACH/SVHC_SOURCE: REACH DECLARATION; REACH/SVHC_STATUS: UNAFFECTED; ROHS: Compliant; Rated Voltage: 50V; Revision: R041; RoHS Status: ROHS_COMPLIANT; Rtd Voltage: 50V; Status: Released; Texas Part Status: Under Review; Type: Capacitor; Vendor: MURATA; Vendor Part Number: GRM0335C1H3R0BA01J; Vendor Part Status: Active; Weight: 0.00033g
C58 = CAPACITOR: CAPACITOR, CERAMIC C0G/NP0, 2.6pF, 50V, -0.1pF/+0.1pF, -55DEGC/+125DEGC, 0201, SMD; ALT_SYMBOLS: CAPC0603X35B2L,CAPC0603X35B2M; Additional Datasheet URL: https://www.murata.com/en-us/products/productdetail?partno=GRM0335C1H2R6BA01%23; Budgetary Price: 0.004 EUR; Country of Origin: China,Japan,Philippines; Datasheet URL: https://search.murata.co.jp/Ceramy/image/img/A01X/G101/ENG/GRM0335C1H2R6BA01-01A.pdf; Dielectric Type: C0G/NP0; Lead Time: 12; Mass: 0.00033g; Maximum Operating Temperature: +125DEGC; Maximum Tolerance: +0.1pF; Minimum Operating Temperature: -55DEGC; Minimum Tolerance: -0.1pF; Mounting Type: SMD; NOTEfied URL: https://notefied-dynamic-precision.com/NOTEfiedWebInterface/part/show?partNumber=02-06140; PCB Package: 0201; Packing Size: 50000; Packing Type: Tape & Reel; Part Number: 02-06140; Part Type: Capacitor|CERAMIC|0201|STANDARD; REACH/SVHC Compliance: Compliant; REACH/SVHC Details: SVHC List Version Jan 23, 2024 (240); REACH/SVHC Source: REACH Declaration; REACH/SVHC Status: Unaffected; ROHS: Compliant; Rated Voltage: 50V; Revision: R042; Status: Released; Texas Part Status: Under Review; Type: Capacitor; Vendor: MURATA; Vendor Part Number: GRM0335C1H2R6BA01J; Vendor Part Status: Active
C59 = CAPACITOR: CAPACITOR, CERAMIC C0G/NP0, 3pF, 50V, -0.1pF/+0.1pF, -55DEGC/+125DEGC, 0201, SMD; ALT_SYMBOLS: CAPC0603X35B2L,CAPC0603X35B2M; Additional Datasheet URL: https://www.murata.com/en-us/products/productdetail?partno=GRM0335C1H3R0BA01%23; Budgetary Price: 0.00272 USD; Country of Origin: China,Japan,Philippines; Datasheet URL: https://search.murata.co.jp/Ceramy/image/img/A01X/G101/ENG/GRM0335C1H3R0BA01-01A.pdf; Dielectric Type: C0G/NP0; Lead Time: 11; Mass: 0.00033g; Maximum Operating Temperature: +125DEGC; Maximum Tolerance: +0.1pF; Minimum Operating Temperature: -55DEGC; Minimum Tolerance: -0.1pF; Mounting Type: SMD; NOTEfied URL: https://notefied-dynamic-precision.com/NOTEfiedWebInterface/part/show?partNumber=02-06144; PCB Package: 0201; Packing Size: 50000; Packing Type: Tape & Reel; Part Number: 02-06144; Part Type: Capacitor|CERAMIC|0201|STANDARD; REACH/SVHC Compliance: Compliant; REACH/SVHC Details: SVHC List Version Jan 23, 2024 (240); REACH/SVHC Source: REACH Declaration; REACH/SVHC Status: Unaffected; ROHS: Compliant; Rated Voltage: 50V; Revision: R041; Status: Released; Texas Part Status: Under Review; Type: Capacitor; Vendor: MURATA; Vendor Part Number: GRM0335C1H3R0BA01J; Vendor Part Status: Active
C60 = CAPACITOR: CAPACITOR, CERAMIC C0G/NP0, 7pF, 50V, -0.1pF/+0.1pF, -55DEGC/+125DEGC, 0201, SMD; ALT_SYMBOLS: CAPC0603X35B2L,CAPC0603X35B2M; Additional Datasheet URL: https://www.murata.com/en-us/products/productdetail?partno=GRM0335C1H7R0BA01%23; Budgetary Price: 0.00272 USD; Country of Origin: China,Japan,Philippines; Datasheet URL: https://search.murata.co.jp/Ceramy/image/img/A01X/G101/ENG/GRM0335C1H7R0BA01-01A.pdf; Dielectric Type: C0G/NP0; Lead Time: 11; Mass: 0.00033g; Maximum Operating Temperature: +125DEGC; Maximum Tolerance: +0.1pF; Minimum Operating Temperature: -55DEGC; Minimum Tolerance: -0.1pF; Mounting Type: SMD; NOTEfied URL: https://notefied-dynamic-precision.com/NOTEfiedWebInterface/part/show?partNumber=02-06184; PCB Package: 0201; Packing Size: 50000; Packing Type: Tape & Reel; Part Number: 02-06184; Part Type: Capacitor|CERAMIC|0201|STANDARD; REACH/SVHC Compliance: Compliant; REACH/SVHC Details: SVHC List Version Jan 23, 2024 (240); REACH/SVHC Source: REACH Declaration; REACH/SVHC Status: Unaffected; ROHS: Compliant; Rated Voltage: 50V; Revision: R041; Status: Released; Texas Part Status: Under Review; Type: Capacitor; Vendor: MURATA; Vendor Part Number: GRM0335C1H7R0BA01J; Vendor Part Status: Active
C62 = CAPACITOR: CAPACITOR, CERAMIC C0G/NP0, 1.5pF, 50V, -0.1pF/+0.1pF, -55DEGC/+125DEGC, 0201, SMD; ALT_SYMBOLS: CAPC0603X35B2L,CAPC0603X35B2M; Additional Datasheet URL: https://www.murata.com/en-eu/products/productdetail?partno=GRM0335C1H1R5BA01%23; Budgetary Price: 0.00272 USD; Country of Origin: China,Japan,Philippines; Datasheet URL: https://search.murata.co.jp/Ceramy/image/img/A01X/G101/ENG/GRM0335C1H1R5BA01-01A.pdf; Dielectric Type: C0G/NP0; Lead Time: 11; Mass: 0.00033g; Maximum Operating Temperature: +125DEGC; Maximum Tolerance: +0.1pF; Minimum Operating Temperature: -55DEGC; Minimum Tolerance: -0.1pF; Mounting Type: SMD; NOTEfied URL: https://notefied-dynamic-precision.com/NOTEfiedWebInterface/part/show?partNumber=02-06129; PCB Package: 0201; Packing Size: 50000; Packing Type: Tape & Reel; Part Number: 02-06129; Part Type: Capacitor|CERAMIC|0201|STANDARD; REACH/SVHC Compliance: Compliant; REACH/SVHC Details: SVHC List Version Jul 7, 2017; REACH/SVHC Source: REACH Declaration; REACH/SVHC Status: Unaffected; ROHS: Compliant; Rated Voltage: 50V; Revision: R034; Status: Released; Texas Part Status: Under Review; Type: Capacitor; Vendor: MURATA; Vendor Part Number: GRM0335C1H1R5BA01J; Vendor Part Status: Active
C63 = CAPACITOR: CAPACITOR, CERAMIC C0G/NP0, 4.3pF, 50V, -0.1pF/+0.1pF, -55DEGC/+125DEGC, 0201, SMD; ALT_SYMBOLS: CAPC0603X35B2L,CAPC0603X35B2M; Additional Datasheet URL: https://search.murata.co.jp/Ceramy/image/img/A01X/G101/ENG/GRM0335C1H4R3BA01-01A.pdf; Budgetary Price: 0.01 EUR; Capacitance: 4.3pF; Country of Origin: China,Japan,Philippines; Datasheet URL: http://www.murata.com/en-eu/api/pdfdownloadapi?cate=luCeramicCapacitorsSMD&partno=GRM0335C1H4R3BA01%23; Dielectric Type: C0G/NP0; Lead Time: 24; Mass: 0.00033g; Maximum Operating Temperature: +125DEGC; Maximum Tolerance: +0.1pF; Minimum Operating Temperature: -55DEGC; Minimum Tolerance: -0.1pF; Mounting Type: SMD; NOTEfied URL: https://notefied-dynamic-precision.com/NOTEfiedWebInterface/part/show?partNumber=02-06157; PCB Package: 0201; Packing Size: 50000; Packing Type: Tape & Reel; Part Number: 02-06157; Part Type: Capacitor|CERAMIC|0201|STANDARD; REACH/SVHC Compliance: Compliant; REACH/SVHC Details: SVHC List Version Jul 7, 2017; REACH/SVHC Source: REACH Declaration; REACH/SVHC Status: Unaffected; ROHS: Compliant; Rated Voltage: 50V; Revision: R033; Status: Released; Texas Part Status: Under Review; Type: Capacitor; Vendor: MURATA; Vendor Part Number: GRM0335C1H4R3BA01J; Vendor Part Status: Active
CR1 = DIODE_TVS_BIDIR_S: DIODE, PROTECTION, TVS, BID, 6.7V, 15W, -40DEGC/+125DEGC, X1SON2, SMD; Additional Datasheet URL: https://www.ti.com/lit/ml/mpss034c/mpss034c.pdf; AutoDoc File: https://notefied-dynamic-precision.com/DB/Apps/Desktop/Item/Object.aspx?id=118028; BU Name: DYNAMIC PRECISION GDANSK; Budget Currency: USD; Budget Price: 0.08; Budgetary Price: 0.144 USD; Client Status: UNDER_REVIEW; Datasheet URL: https://www.ti.com/lit/gpn/tpd1e0b04; Datasheet URL 1: http://www.ti.com/lit/ds/symlink/tpd1e0b04.pdf; Datasheet URL 2: http://www.ti.com/lit/ml/mpss034c/mpss034c.pdf; Lead Time: 12; Mass: 0.0031g; Max Oper Temp: +125DEGC; Maximum Operating Temperature: +125DEGC; Min Oper Temp: -40DEGC; Minimum Operating Temperature: -40DEGC; Mounting Type: SMD; NOTEfied URL: https://notefied-dynamic-precision.com/NOTEfiedWebInterface/part/show?partNumber=14-06704; PCB Package: SON2; Packing Size: 10000; Packing Type: Tape & Reel; Part Number: 14-06704; Part Type: Diode|PROTECTION; REACH/SVHC Compliance: Compliant; REACH/SVHC Details: SVHC List Version Jan 12, 2017; REACH/SVHC Source: REACH Declaration; REACH/SVHC Status: Unaffected; ROHS: Compliant; Rated Power: 15W; Rated Voltage: 6.7V; Revision: R023; RoHS Status: ROHS_COMPLIANT; Rtd Power: 15W; Rtd Voltage: 6.7V; Status: Released; Texas Part Status: Under Review; Type: Diode; Vendor: TEXAS INSTRUMENTS; Vendor Part Number: TPD1E0B04DPYR; Vendor Part Status: Active; Weight: 0.0031g
FL1 = FILTER_2PIN: FILTER, EMI, FERRITE BEAD, 1500@100MHz, -25%/+25%, -55DEGC/+125DEGC, 0603, SMD; ALT_SYMBOLS: FIL_BLM18HE152SN1DL,FIL_BLM18HE152SN1DM; Additional Datasheet URL: https://www.murata.com/en-us/products/productdetail?partno=BLM18HE152SN1%23; AutoDoc File: http://notefied-dynamic-precision.com/DB/Apps/Desktop/Item/Object.aspx?id=85575; Budget Currency: EUR; Budget Price: 0.085; Budgetary Price: 0.07 EUR; CLASS: DISCRETE; Country of Origin: Japan,Thailand; Datasheet URL: https://www.murata.com/products/productdata/8796741599262/ENFA0004.pdf?1694143827000; Datasheet URL 1: http://search.murata.co.jp/Ceramy/image/img/PDF/ENG/L0110S0101BLM18H.pdf; Datasheet URL 2: http://search.murata.co.jp/Ceramy/image/img/PDF/ENG/L0110S0101BLM18H.pdf; FPLIST: FIL_BLM18HE152SN1DN,FIL_BLM18HE152SN1DL,FIL_BLM18HE152SN1DM; Frequency: 100MHz; Impedance: 1500; Inductance: N/A; Lead Time: 8; MPN: BLM18HE152SN1D; MPN Status: ACTIVE; Manufacturer: MURATA; Mass: 0.006g; Max Oper Temp: +125DEGC; Max Tol: +25%; Maximum Operating Temperature: +125DEGC; Maximum Tolerance: +25%; Min Oper Temp: -55DEGC; Min Tol: -25%; Minimum Operating Temperature: -55DEGC; Minimum Tolerance: -25%; Mounting Type: SMD; NOTE Status: PREFERRED; NOTEfied URL: https://notefied-dynamic-precision.com/NOTEfiedWebInterface/part/show?partNumber=04-00470; PCB Package: 0603; Packing Size: 4000; Packing Type: Tape & Reel; Part Number: 04-00470; Part Type: Filter|EMI|FERRITE BEAD|0603; REACH/SVHC Compliance: Compliant; REACH/SVHC Details: SVHC List Version Jan 23, 2024 (240); REACH/SVHC Source: REACH Declaration; REACH/SVHC Status: Unaffected; ROHS: Compliant; Rated Current: 0.5A; Rated Voltage: N/A; Revision: R040; RoHS Status: ROHS_COMPLIANT; Rtd Current: 0.5A; Status: Released; Texas Part Status: Under Review; Type: Filter; Vendor: MURATA; Vendor Part Number: BLM18HE152SN1D; Vendor Part Status: Active; WEIGHT: 0.006g
J3 = CONN_COAX_1_4: CONNECTOR, COAX, RF, FEMALE, STRAIGHT, 1 PIN, SMD; ALT_SYMBOLS: HUSTSAN_SMA10V21TGGL,HUSTSAN_SMA10V21TGGM; Additional Datasheet URL: http://www.hustsan.com.tw/cgi-bin/productfn/pdt_detail_lst.pl?ProdID=143; AutoDoc File: https://notefied-dynamic-precision.com/DB/Apps/Desktop/Item/Object.aspx?id=84956; BU Name: DYNAMIC PRECISION GDANSK; Budget Currency: N/A; Budget Price: N/A; Client Status: UNDER_REVIEW; Country of Origin: Taiwan; Datasheet URL: http://www.hustsan.com.tw/uploaddir/product/SMA-10V21.pdf; Datasheet URL 1: http://www.hustsan.com.tw/uploaddir/product/SMA-10V21.pdf; Datasheet URL 2: http://www.hustsan.com.tw/cgi-bin/productfn/pdt_detail_lst.pl?ProdID=143; FPLIST: HUSTSAN_SMA10V21TGGAN,HUSTSAN_SMA10V21TGGN; Mass: N/A; Mounting Type: SMD; NOTEfied URL: https://notefied-dynamic-precision.com/NOTEfiedWebInterface/part/show?partNumber=06-02188; No Of Pos: 1; Number of Positions: 1; Packing Size: 350; Packing Type: Tape & Reel; Part Number: 06-02188; Part Type: Connector|COAX|RF; REACH/SVHC Compliance: Compliant; REACH/SVHC Details: SVHC List Version Jun 20, 2016; REACH/SVHC Source: REACH Declaration; REACH/SVHC Status: Unaffected; REACH/SVHC_COMPLIANCE: COMPLIANT; REACH/SVHC_DETAILS: SVHC LIST VERSION Jan 12, 2016; REACH/SVHC_SOURCE: REACH DECLARATION; REACH/SVHC_STATUS: UNAFFECTED; ROHS: Compliant; Revision: R022; RoHS Status: ROHS_COMPLIANT; Status: Released; Texas Part Status: Under Review; Type: Connector; Vendor: HUS-TSAN; Vendor Part Status: Active; Weight: N/A
L1 = INDUCTOR: INDUCTOR, STANDARD, FERRITE CORE, 6.8uH, -20%/+20%, 0.11A, -55DEGC/+125DEGC, 0805, SMD; ALT_SYMBOLS: INDC2012X150A2L,INDC2012X150A2M; Additional Datasheet URL: https://product.tdk.com/en/search/inductor/inductor/smd/info?part_no=MLZ2012N6R8LT000; AutoDoc File: https://notefied-dynamic-precision.com/DB/Apps/Desktop/Item/Object.aspx?id=102853; BU Name: DYNAMIC PRECISION GDANSK; Budget Currency: EUR; Budget Price: 0.059; Budgetary Price: 0.04635 USD; Client Status: UNDER_REVIEW; Core Material: FERRITE; Country of Origin: Japan; Datasheet URL: https://product.tdk.com/system/files/dam/doc/product/inductor/inductor/smd/catalog/inductor_commercial_decoupling_mlz2012_en.pdf; Datasheet URL 1: https://product.tdk.com/info/en/catalog/datasheets/inductor_commercial_decoupling_mlz2012_en.pdf; Datasheet URL 2: N/A; Lead Time: 15; MPN: CKS2125100M-T; MPN Status: ACTIVE; Manufacturer: TAIYO YUDEN; Mass: 0.01g; Max Oper Temp: +125DEGC; Max Tol: +20%; Maximum Operating Temperature: +125DEGC; Maximum Tolerance: +20%; Min Oper Temp: -55DEGC; Min Tol: -20%; Minimum Operating Temperature: -55DEGC; Minimum Tolerance: -20%; Mounting Type: SMD; NOTE Status: PREFERRED; NOTEfied URL: https://notefied-dynamic-precision.com/NOTEfiedWebInterface/part/show?partNumber=03-07266; Old Footprint: INDC2012X150N; PCB Package: 0805; Packing Size: 4000; Packing Type: Tape & Reel; Part Number: 03-07266; Part Type: Inductor|STANDARD|CHIP|0805; REACH/SVHC Compliance: Compliant; REACH/SVHC Details: SVHC List Version Jan 12, 2017 (173); REACH/SVHC Source: REACH Declaration; REACH/SVHC Status: Unaffected; REACH/SVHC_COMPLIANCE: COMPLIANT; REACH/SVHC_DETAILS: SVHC LIST VERSION Dec 17, 2015; REACH/SVHC_SOURCE: REACH DECLARATION; REACH/SVHC_STATUS: UNAFFECTED; ROHS: Compliant; Rated Current: 0.11A; Resistance: 0.25; Revision: R036; RoHS Status: ROHS_COMPLIANT; Rtd Current: 1.1A; Status: Released; Texas Part Status: Under Review; Type: Inductor; Vendor: TDK GLOBAL; Vendor Part Number: MLZ2012N6R8LT000; Vendor Part Status: Active; Weight: 0.01g
L11 = INDUCTOR: INDUCTOR, RF, CHIP, NON-MAGNETIC CORE, 20nH, -3%/+3%, 0.15A, -55DEGC/+125DEGC, 0201, SMD; ALT_SYMBOLS: INDC0603X33A2L,INDC0603X33A2M; Additional Datasheet URL: https://search.murata.co.jp/Ceramy/image/img/P02/JELF243C-0015.pdf; Datasheet URL: https://www.murata.com/-/media/webrenewal/support/library/catalog/products/inductor/chip/o05e.ashx?la=en-gb; Frequency: 2.2GHz; Mass: 0.0002g; Maximum Operating Temperature: +125DEGC; Maximum Tolerance: +3%; Minimum Operating Temperature: -55DEGC; Minimum Tolerance: -3%; Mounting Type: SMD; NOTEfied URL: https://notefied-dynamic-precision.com/NOTEfiedWebInterface/part/show?partNumber=03-08076; PCB Package: 0201; Packing Size: 50000; Packing Type: Tape & Reel; Part Number: 03-08076; Part Type: Inductor|RF|CHIP|0201; REACH/SVHC Compliance: Compliant; REACH/SVHC Details: SVHC List Version Jul 16, 2019; REACH/SVHC Source: REACH Declaration; REACH/SVHC Status: Unaffected; ROHS: Compliant; Resistance: 2.3; Revision: R006; Status: Released; Texas Part Status: Under Review; Type: Inductor; Vendor: MURATA; Vendor Part Number: LQP03TN20NH02J; Vendor Part Status: Active
